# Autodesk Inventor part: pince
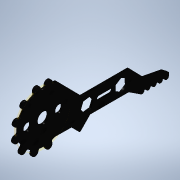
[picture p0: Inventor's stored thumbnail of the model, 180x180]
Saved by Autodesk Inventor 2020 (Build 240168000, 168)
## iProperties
Created: 2021-10
Part Number: pince
Material: Générique
Document SubType Name: Modeling
Designer: bruno
Density: 5.41165 g/cm^3
Appearance: Noir
Mass: 4 g
Surface Area: 17.6187 cm^2
Volume: 0.739146 cm^3
Author: bruno
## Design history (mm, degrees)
sketch "Esquisse1"
  geometry: L1 (-0.244, -38.167)-(-0.244, -17.144); L2 (-9.818, -12.478)-(-13.216, -15.844); L3 (-6.724, -44.413)-(-8.393, -53.057); L4 (-8.393, -53.057)-(-10.196, -55.455); L5 (-10.196, -55.455)-(-11.607, -55.455); L6 (0, 7)-(0, -8.75); L7 (-12.196, -55.455)-(-12.196, -55.476); L8 (-11.599, -44.655)-(-11.599, -45.356); L9 (11.244, 3.975)-(10.788, 3.82); L10 (11.864, 1.062)-(11.343, 0.947); L11 (10.951, 0.571)-(10.951, 0.458); L12 (9.199, 5.97)-(9.255, 5.873); L13 (9.743, 6.851)-(9.35, 6.491); L14 (7.75, 9.065)-(7.433, 8.702); L15 (4.981, 9.77)-(5.079, 9.713); L16 (5.012, 10.805)-(4.852, 10.297); L17 (2.179, 11.726)-(2.086, 11.252); L18 (-0.571, 10.951)-(-0.458, 10.951); L19 (-1.062, 11.864)-(-0.947, 11.343); L20 (-3.975, 11.244)-(-3.82, 10.788); L21 (-5.97, 9.199)-(-5.873, 9.255); L22 (-6.851, 9.743)-(-6.491, 9.35); L23 (-9.065, 7.75)-(-8.702, 7.433); L24 (-9.77, 4.981)-(-9.713, 5.079); L25 (-10.805, 5.012)-(-10.297, 4.852); L26 (-11.726, 2.179)-(-11.252, 2.086); L27 (-10.951, -0.571)-(-10.951, -0.458); L28 (-11.864, -1.062)-(-11.343, -0.947); L29 (-11.244, -3.975)-(-11.288, -3.99); L30 (10.167, -4.111)-(10.119, -4.213); L31 (11.871, -1.149)-(11.391, -1.097); L32 (11.201, -4.051)-(10.681, -3.936); L33 (24.231, -59.591)-(24.231, 5.458); L34 (24.231, 5.458)-(-15.993, 5.458); L35 (-15.993, 5.458)-(-15.993, -59.591); L36 (-15.993, -59.591)-(24.231, -59.591); L37 (-13.213, -16.557)-(-8.957, -20.692); L38 (-8.957, -20.692)-(-8.957, -37.719); L39 (-11.607, -52.755)-(-11.607, -53.455); L40 (-11.607, -47.355)-(-11.607, -48.055); L41 (-11.607, -50.055)-(-11.607, -50.755); L42 (-11.599, -44.208)-(-11.607, -44.193); L43 (-4.7, -24.661)-(-4.7, -29.925); L44 (-5.7, -24.661)-(-5.7, -29.925); L45 (-3.7, -29.925)-(-3.7, -24.661); L46 (-0.244, -38.167)-(-0.244, -38.182); L47 (-9.818, -12.478)-(-9.733, -5.173); L48 (-10.788, -3.82)-(-11.288, -3.99); L49 (10.946, -6.1)-(-0.244, -17.144); L50 (10.946, -0.574)-(10.946, -0.626); L51 (10.946, -4.623)-(10.946, -6.1); L52 (-11.607, -54.455)-(-11.207, -54.455); L53 (-0.244, -38.182)-(-6.742, -44.504); L54 (-12.464, -43.067)-(-8.957, -37.719); C1 r 2.5 at (0, 0); C2 r 1.75 at (0, 7); A1 r 1.75 centre (0, -7) between (0, -8.75) and (1.658, -7.559); A2 r 1 centre (-11.657, -43.657) between (-12.464, -43.067) and (-11.599, -44.655); A3 r 1 centre (-11.573, -46.355) between (-11.599, -45.356) and (-11.607, -47.355); A4 r 1 centre (-11.607, -49.055) between (-11.607, -48.055) and (-11.607, -50.055); A5 r 1 centre (-11.607, -51.755) between (-11.607, -50.755) and (-11.607, -52.755); A6 r 1 centre (-11.607, -54.455) between (-11.607, -53.455) and (-11.607, -55.455); A7 r 1.5 centre (11.729, 2.556) between (11.864, 1.062) and (11.244, 3.975); A8 r 0.5 centre (10.627, 4.293) between (10.163, 4.106) and (10.788, 3.82); A9 r 0.5 centre (11.451, 0.458) between (11.343, 0.947) and (10.951, 0.458); A10 r 0.5 centre (9.688, 6.123) between (9.35, 6.491) and (9.255, 5.873); A11 r 1.5 centre (8.879, 8.078) between (9.743, 6.851) and (7.75, 9.065); A12 r 0.5 centre (7.056, 9.031) between (6.749, 8.637) and (7.433, 8.702); A13 r 0.5 centre (5.329, 10.146) between (4.852, 10.297) and (5.079, 9.713); A14 r 1.5 centre (3.651, 11.435) between (5.012, 10.805) and (2.179, 11.726); A15 r 0.5 centre (1.595, 11.349) between (1.526, 10.854) and (2.086, 11.252); A16 r 0.5 centre (-0.458, 11.451) between (-0.947, 11.343) and (-0.458, 10.951); A17 r 1.5 centre (-2.556, 11.729) between (-1.062, 11.864) and (-3.975, 11.244); A18 r 0.5 centre (-4.293, 10.627) between (-4.106, 10.163) and (-3.82, 10.788); A19 r 0.5 centre (-6.123, 9.688) between (-6.491, 9.35) and (-5.873, 9.255); A20 r 1.5 centre (-8.078, 8.879) between (-6.851, 9.743) and (-9.065, 7.75); A21 r 0.5 centre (-9.031, 7.056) between (-8.637, 6.749) and (-8.702, 7.433); A22 r 0.5 centre (-10.146, 5.329) between (-10.297, 4.852) and (-9.713, 5.079); A23 r 1.5 centre (-11.435, 3.651) between (-10.805, 5.012) and (-11.726, 2.179); A24 r 0.5 centre (-11.349, 1.595) between (-10.854, 1.526) and (-11.252, 2.086); A25 r 0.5 centre (-11.451, -0.458) between (-11.343, -0.947) and (-10.951, -0.458); A26 r 1.5 centre (-11.729, -2.556) between (-11.864, -1.062) and (-11.244, -3.975); A27 r 0.5 centre (-10.627, -4.293) between (-10.163, -4.106) and (-10.788, -3.82); A28 r 0.5 centre (11.445, -0.6) between (10.946, -0.574) and (11.391, -1.097); A29 r 0.5 centre (10.572, -4.424) between (10.681, -3.936) and (10.119, -4.213); A30 r 1.5 centre (11.71, -2.64) between (11.512, -4.127) and (11.871, -1.149); A31 r 10.961 centre (0, 0) between (-10.854, 1.526) and (-10.951, -0.458); A32 r 10.961 centre (0, 0) between (-8.637, 6.749) and (-9.713, 5.079); A33 r 10.961 centre (0, 0) between (-4.106, 10.163) and (-5.873, 9.255); A34 r 10.961 centre (0, 0) between (1.526, 10.854) and (-0.458, 10.951); A35 r 10.961 centre (0, 0) between (10.163, 4.106) and (9.255, 5.873); A36 r 10.961 centre (0, 0) between (6.749, 8.637) and (5.079, 9.713); A37 r 0.5 centre (-12.864, -16.199) between (-13.216, -15.844) and (-13.213, -16.557); A38 r 1 centre (-4.7, -24.661) between (-3.7, -24.661) and (-5.7, -24.661); A39 r 1 centre (-4.7, -29.925) between (-5.7, -29.925) and (-3.7, -29.925); A40 r 7.739 centre (0, 0) between (5.487, 5.458) and (1.658, -7.559); A41 r 0.5 centre (-10.222, -4.155) between (-9.722, -4.161) and (-10.383, -3.682); A42 r 0.5 centre (11.446, -4.623) between (11.512, -4.127) and (10.946, -4.623); A43 r 10.964 centre (0, 0) between (10.946, -0.626) and (10.951, 0.523); A44 r 10.964 centre (0, 0) between (10.135, -4.181) and (10.146, -4.155); A45 r 10.964 centre (0, 0) between (10.185, 4.058) and (9.223, 5.928); A46 r 10.964 centre (0, 0) between (6.791, 8.607) and (5.023, 9.745); A47 r 10.964 centre (0, 0) between (1.578, 10.85) and (-0.523, 10.951); A48 r 10.964 centre (0, 0) between (-4.058, 10.185) and (-5.928, 9.223); A49 r 10.964 centre (0, 0) between (-8.607, 6.791) and (-9.745, 5.023); A50 r 10.964 centre (0, 0) between (-10.85, 1.578) and (-10.951, -0.523); A51 r 10.964 centre (0, 0) between (-10.185, -4.058) and (-9.787, -4.942); A52 r 0.5 centre (-10.233, -5.167) between (-9.733, -5.173) and (-9.787, -4.942); 28 further points; 1 other entity
  constraints: 116 point on circle, 102 end point, 54 centre point, 27 point on line, 17 tangent, 7 vertical, 4 coincident, 4 perpendicular, 2 horizontal, 2 parallel, 1 midpoint, 123 other
  dimensions: "d0" = 5 diameter of C1; "d1" = 3.5 diameter of C2; "d2" = 3.5 diameter of A1; "d3" = 7 distance of point (0, 0) L6.start; "d4" = 7 distance of point (0, 0) A1.centre; "d17" = 3 distance of L3.end L4.end; "d18" = 2 distance of L7.end L4.end; "d20" = 2 diameter of A3; "d21" = 2 diameter of A2; "d22" = 2 diameter of A4; "d24" = 2 diameter of A5; "d25" = 2.7 distance of A2.centre A3.centre; "d26" = 2.7 distance of A3.centre A4.centre; "d27" = 2.7 distance of A5.centre A4.centre; "d28" = 2 diameter of A6; "d29" = 2.7 distance of L52.start A5.centre; "d30" = 3 diameter of A7; "d31" = 0.5 radius of A8 (derived); "d32" = 0.5 radius of A9 (derived); "d35" = 180 deg dimension on A31.centre A9.centre A25.centre; "d39" = 25 deg dimension on C1.centre L30.start L11.start; "d132" = 0.5 radius of A37 (derived); "d136" = 2 diameter of A39; "d154" = 0.5 radius of A41 (derived); "d156" = 0.5 radius of A42 (derived); "d167" = 0.5 radius of A52 (derived); "d178" = 0.4 distance of L52.start L52.end
extrude "Extrusion2" new body sketch "Esquisse1" distance "d48" = 1; taper "d49" = 0 deg
sketch "Esquisse2"
  geometry: L1 (21.242, -7.012)-(18.385, -7.425); L2 (18.385, -7.425)-(16.598, -5.157); L3 (16.598, -5.157)-(17.669, -2.476); L4 (17.669, -2.476)-(20.526, -2.063); L5 (20.526, -2.063)-(22.312, -4.331); L6 (22.312, -4.331)-(21.242, -7.012); L7 (34.555, -7.629)-(32.006, -6.273); L8 (32.006, -6.273)-(31.907, -3.388); L9 (31.907, -3.388)-(34.356, -1.859); L10 (34.356, -1.859)-(36.904, -3.215); L11 (36.904, -3.215)-(37.003, -6.1); L12 (37.003, -6.1)-(34.555, -7.629); L13 (55.455, -11.607)-(55.455, -10.196) reference; L14 (20.692, -8.957)-(37.719, -8.957) reference; 9 further points; 1 other entity
  constraints: 24 end point, 27 other
  dimensions: "d50" = 5 distance between parallel lines of L5 L2; "d51" = 5 distance between parallel lines of L8 L11; "d56" = 15 distance of point (19.455, -4.744) point (34.455, -4.744); "d57" = 21 distance from line of L13 point (34.455, -4.744); "d171" = 4.5 dimension on point (19.455, -4.744); "d172" = 4.5 dimension on point (34.455, -4.744)
extrude "Extrusion3" cut sketch "Esquisse2" distance "d54" = 10; taper "d55" = 0 deg
sketch "Esquisse3"
  geometry: C1 r 12 at (0, 0); 1 further point
  constraints: 1 centre point, 1 coincident
  dimensions: "d62" = 24 diameter of C1
feature "SrfExtrusion1" sketch "Esquisse3" dims "d63" = 1, "d64" = 0
node "Solide2"
body "Srf1"
node "Image1"
other parameters: "d5" = 22.5
